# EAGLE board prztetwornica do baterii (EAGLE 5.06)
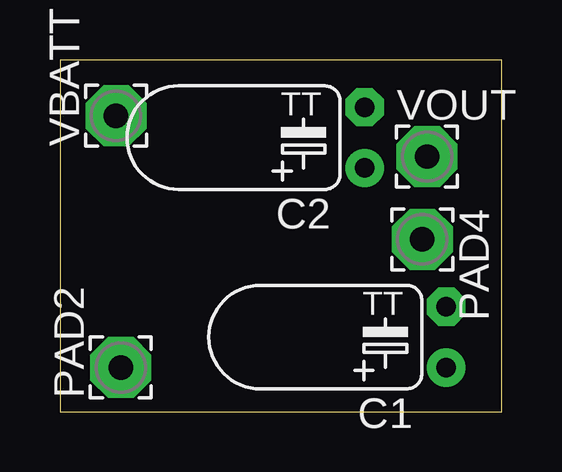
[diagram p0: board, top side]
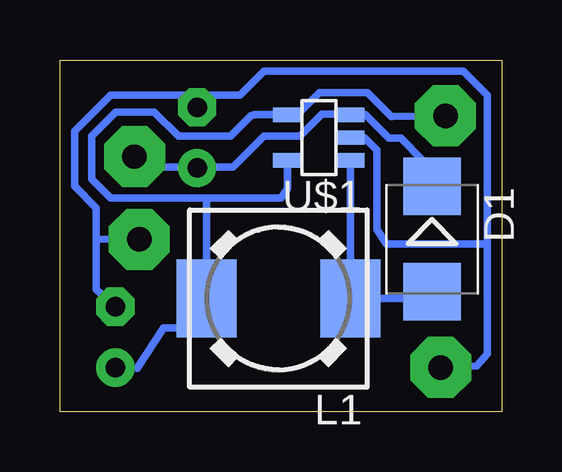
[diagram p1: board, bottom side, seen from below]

Size 18.42 x 14.67 mm. Coordinates in mm from the lower left corner, seen from the top.
Outline: 0,0 18.42,0 18.42,14.67 0,14.67 0,0
Copper layers (1*16): Top 0.035mm / dielectric 1.5mm / Bottom 0.035mm
Design rules "default": minimum track width 10mil, minimum drill 24mil, track to track 8mil, track to pad 8mil, pad to pad 8mil, via to via 8mil, smd to smd 8mil, copper to edge 40mil, drill to drill 8mil, minimum pad ring 10mil, minimum via ring 8mil, stop-mask expansion 4mil, vias tented up to drill 0mil, thermal gap 10mil

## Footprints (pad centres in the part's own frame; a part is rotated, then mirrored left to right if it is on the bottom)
TT2D4L = drill 0.813 pad 1.6 round: + -1.27,0 | drill 0.813 pad 1.6 octagon: - 1.27,0
SMB = smd 2.4 x 2.4: A 2.2,0; C -2.2,0
DR74 = smd 2.5 x 3.25: 1 -3,0; 2 3,0
2,54/1,0 = drill 1.016 pad 2.54 octagon: 1 0,0
SOT23-5 = smd 0.6 x 1.2: 1 -0.95,-1.306; 2 0,-1.306; 3 0.95,-1.306; 4 0.95,1.306; 5 -0.95,1.306

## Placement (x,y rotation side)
C1  100u  [TT2D4L]  16.11,3.11 90 top
C2  100u  [TT2D4L]  12.7,11.43 90 top
D1  MBRS130LT3  [SMB]  2.9,7.2 270 bottom
L1  DR74  [DR74]  9.31,4.72 180 bottom
PAD2  [2,54/1,0]  2.54,1.84 90 top
PAD4  [2,54/1,0]  15.11,7.19 270 top
U$1  SP6641  [SOT23-5]  7.62,11.43 90 bottom
VBATT  [2,54/1,0]  2.34,12.34 90 top
VOUT  [2,54/1,0]  15.31,10.64 0 top

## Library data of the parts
C1 C2 = rcl
D1 = diode
L1 = inductors
PAD2 PAD4 VBATT VOUT = wirepad
U$1 = sipex

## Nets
GND: C1.- C2.- PAD2.1 PAD4.1 U$1.2
N$1: D1.A L1.1 U$1.1
N$4: C1.+ L1.2 U$1.4 U$1.5 VBATT.1
N$6: C2.+ D1.C U$1.3 VOUT.1

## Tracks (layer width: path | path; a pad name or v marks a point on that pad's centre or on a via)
GND
  Bottom 0.305: 0.6,7 4.8,7 5.2,7.6 5.2,10.9 5.73,11.43 U$1.2 6.6,11.4 6.6,11.5 | 0.6,7 0.6,2.4 1.04,1.9 PAD2.1 | 0.6,7 0.6,13.2 1.6,14.2 9.9,14.2 10.9,13.2 12.7,13.2 | 0.6,7 0.6,6.7 | C1.- 16.9,5.1 16.9,7.2 | 16.9,7.2 16.9,8.5 17.8,9.4 17.8,11.7 16.3,13.2 12.7,13.2 | PAD4.1 16.9,7.2 | 12.7,13.2 C2.-
N$1
  Bottom 0.305: L1.1 5.77,4.86 arc-45 5.68,4.88 5.78,4.96 | U$1.1 6.3,10.47 6.3,4.7 6.28,4.72 L1.1 | D1.A 3.18,4.72 L1.1
N$4
  Bottom 0.305: U$1.5 8.93,9.3 9.2,8.9 12.3,8.9 | 12.3,8.9 16.3,8.9 17.1,9.7 17.1,11.5 16.1,12.5 14.5,12.5 13.47,11.5 11.3,11.5 10.51,12.29 arc45 10.29,12.38 U$1.4 8.5,12.4 7.6,13.3 5.6,13.3 4.6,12.3 VBATT.1 | 12.3,8.9 L1.2 13,4.03 13,3.5 14.1,3.5 15.2,1.8 C1.+
N$6
  Bottom 0.305: 12.7,10.2 11.2,10.2 9.9,11.5 8.4,11.5 7.5,12.4 6.4,12.4 U$1.3 5.68,12.38 4.7,11.4 4.2,11.4 3.3,10.5 3.3,9.8 D1.C | 12.7,10.2 C2.+ | 12.7,10.2 14.74,10.2 arc45 14.96,10.29 VOUT.1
